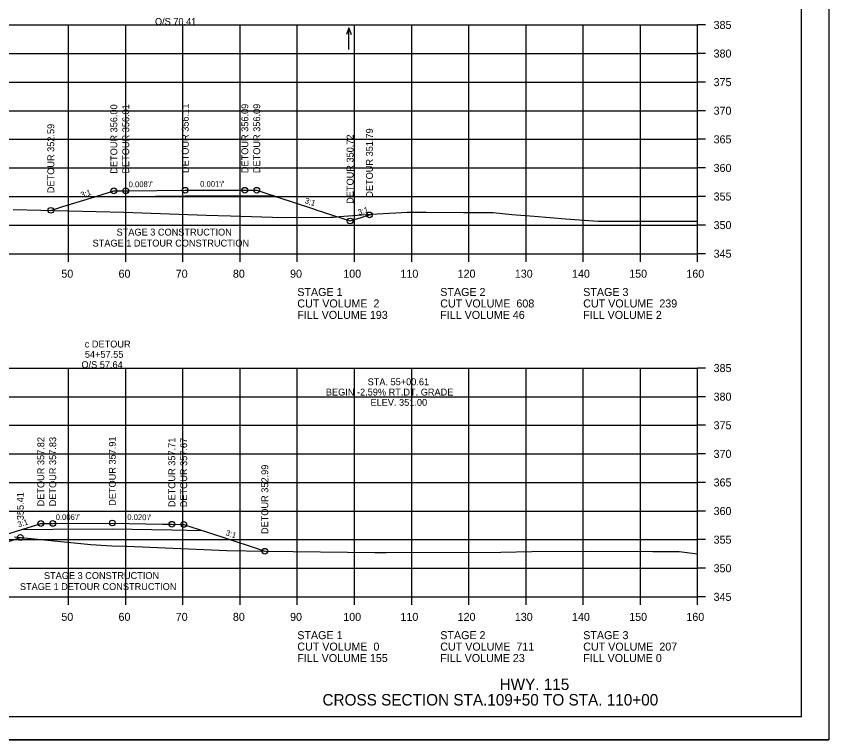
# Model space of a CAD drawing. Extents: x 1630712 to 1632516, y 782146 to 785403.
# Drawn here: x 1632373.8 to 1632515.9, y 783910 to 784036.5 of the extents above; entities that cross this region are included whole.
import ezdxf

# ---------------------------------------------------------------- set-up
doc = ezdxf.new("R2010")
doc.units = 0
for name, color, linetype in [('Notes', 7, 'Continuous'), ('R_Axis', 7, 'Continuous'), ('R_Axis Annot', 7, 'Continuous'), ('R_Border', 7, 'Continuous'), ('R_Detour Subgrade', 7, 'Continuous'), ('R_Detour Surface', 7, 'Continuous'), ('R_Draft', 7, 'Continuous'), ('R_Exist Surface', 7, 'Continuous'), ('R_Fin Surface', 7, 'Continuous'), ('R_Grid', 7, 'Continuous'), ('R_No Plot', 7, 'Continuous'), ('R_Water Annot', 7, 'Continuous'), ('R_Xsect Elev', 7, 'Continuous'), ('R_Xsect Elev Detour', 7, 'Continuous'), ('R_Xsect Slope', 7, 'Continuous')]:
    doc.layers.add(name, color=color, linetype=linetype)

msp = doc.modelspace()

# ---------------------------------------------------------------- linework, layer by layer
at = {"layer": 'R_Axis'}
for p, q in [((1632492.96, 783994.96), (1632492.96, 784034.96)), ((1632494.36, 784034.96), (1632492.96, 784034.96)), ((1632494.36, 784029.96), (1632492.96, 784029.96)), ((1632494.36, 784024.96), (1632492.96, 784024.96)), ((1632494.36, 784019.96), (1632492.96, 784019.96)), ((1632494.36, 784014.96), (1632492.96, 784014.96)), ((1632494.36, 784009.96), (1632492.96, 784009.96)), ((1632494.36, 784004.96), (1632492.96, 784004.96)), ((1632494.36, 783999.96), (1632492.96, 783999.96)), ((1632212.96, 783994.96), (1632492.96, 783994.96)), ((1632382.96, 783993.56), (1632382.96, 783994.96)), ((1632392.96, 783993.56), (1632392.96, 783994.96)), ((1632402.96, 783993.56), (1632402.96, 783994.96)), ((1632412.96, 783993.56), (1632412.96, 783994.96)), ((1632422.96, 783993.56), (1632422.96, 783994.96)), ((1632432.96, 783993.56), (1632432.96, 783994.96)), ((1632442.96, 783993.56), (1632442.96, 783994.96)), ((1632452.96, 783993.56), (1632452.96, 783994.96)), ((1632462.96, 783993.56), (1632462.96, 783994.96)), ((1632472.96, 783993.56), (1632472.96, 783994.96)), ((1632482.96, 783993.56), (1632482.96, 783994.96)), ((1632492.96, 783993.56), (1632492.96, 783994.96)), ((1632494.36, 783994.96), (1632492.96, 783994.96)), ((1632492.96, 783934.96), (1632492.96, 783974.96)), ((1632494.36, 783974.96), (1632492.96, 783974.96)), ((1632494.36, 783969.96), (1632492.96, 783969.96)), ((1632494.36, 783964.96), (1632492.96, 783964.96)), ((1632494.36, 783959.96), (1632492.96, 783959.96)), ((1632494.36, 783954.96), (1632492.96, 783954.96)), ((1632494.36, 783949.96), (1632492.96, 783949.96)), ((1632494.36, 783944.96), (1632492.96, 783944.96)), ((1632494.36, 783939.96), (1632492.96, 783939.96)), ((1632212.96, 783934.96), (1632492.96, 783934.96)), ((1632382.96, 783933.56), (1632382.96, 783934.96)), ((1632392.96, 783933.56), (1632392.96, 783934.96)), ((1632402.96, 783933.56), (1632402.96, 783934.96)), ((1632412.96, 783933.56), (1632412.96, 783934.96)), ((1632422.96, 783933.56), (1632422.96, 783934.96)), ((1632432.96, 783933.56), (1632432.96, 783934.96)), ((1632442.96, 783933.56), (1632442.96, 783934.96)), ((1632452.96, 783933.56), (1632452.96, 783934.96)), ((1632462.96, 783933.56), (1632462.96, 783934.96)), ((1632472.96, 783933.56), (1632472.96, 783934.96)), ((1632482.96, 783933.56), (1632482.96, 783934.96)), ((1632492.96, 783933.56), (1632492.96, 783934.96)), ((1632494.36, 783934.96), (1632492.96, 783934.96))]:
    msp.add_line(p, q, dxfattribs=at)
at = {"layer": 'R_Border'}
for q in [(1632511.14, 784119.42), (1632194.96, 783913.96)]:
    msp.add_line((1632511.14, 783913.96), q, dxfattribs=at)
at = {"layer": 'R_Detour Subgrade'}
for points in [[(1632387.55, 784004.92), (1632392.96, 784004.97), (1632403.37, 784005.06), (1632413.79, 784005.05), (1632418.9, 784005.05)], [(1632374.78, 783946.75), (1632380.19, 783946.79), (1632390.61, 783946.87), (1632401.02, 783946.66), (1632406.3, 783946.57)]]:
    msp.add_lwpolyline(points, dxfattribs=at)
at = {"layer": 'R_Detour Surface'}
for points in [[(1632379.86, 784002.54), (1632381.97, 784003.2), (1632387.55, 784004.92), (1632387.88, 784005.03), (1632390.88, 784005.95), (1632390.9, 784005.95), (1632391.29, 784005.96), (1632392.96, 784005.97), (1632393.49, 784005.97), (1632403.37, 784006.06), (1632403.39, 784006.06), (1632403.58, 784006.06), (1632403.59, 784006.06), (1632413.79, 784006.05), (1632414.84, 784006.05), (1632415.87, 784006.05), (1632417.81, 784005.41), (1632418.9, 784005.05), (1632419.35, 784004.9), (1632419.53, 784004.84), (1632425.78, 784002.79), (1632426.55, 784002.53), (1632427.18, 784002.32), (1632427.37, 784002.26), (1632427.5, 784002.22), (1632432.19, 784000.68), (1632434.13, 784001.29), (1632435.58, 784001.75), (1632436.05, 784001.9)], [(1632370.61, 783945.46), (1632373.86, 783946.47), (1632374.78, 783946.75), (1632377.41, 783947.56), (1632378.11, 783947.78), (1632379.49, 783947.78), (1632380.19, 783947.79), (1632390.6, 783947.87), (1632390.61, 783947.87), (1632399.39, 783947.69), (1632401.02, 783947.66), (1632402.74, 783947.63), (1632403.1, 783947.63), (1632403.83, 783947.39), (1632406.3, 783946.57), (1632406.53, 783946.49), (1632406.92, 783946.36), (1632415.39, 783943.56), (1632417.28, 783942.94)]]:
    msp.add_lwpolyline(points, dxfattribs=at)
at = {"layer": 'R_Exist Surface'}
for points in [[(1632373.29, 784002.71), (1632392.65, 784002.21), (1632407.04, 784001.7), (1632411.25, 784001.61), (1632420.42, 784001.3), (1632428.84, 784001.37), (1632429.31, 784001.35), (1632430.35, 784001.45), (1632435.82, 784001.89), (1632440.17, 784002.11), (1632442.15, 784002.22), (1632443.63, 784002.21), (1632445.47, 784002.2), (1632452.05, 784002.14), (1632457.19, 784002.14), (1632460.47, 784001.84), (1632464.37, 784001.54), (1632469.84, 784001.08), (1632475.6, 784000.67), (1632483.55, 784000.65), (1632486.52, 784000.65), (1632492.96, 784000.64)], [(1632373.51, 783945.47), (1632386.83, 783944.09), (1632390.55, 783943.86), (1632393.13, 783943.81), (1632410.62, 783943.04), (1632417.43, 783942.94), (1632436.49, 783942.71), (1632437.77, 783942.7), (1632438.5, 783942.7), (1632458.54, 783942.8), (1632464, 783942.87), (1632474.44, 783942.94), (1632485.14, 783942.91), (1632489.76, 783942.9), (1632492.96, 783942.5)]]:
    msp.add_lwpolyline(points, dxfattribs=at)
at = {"layer": 'R_Fin Surface'}
msp.add_lwpolyline([(1632244.19, 783961.28), (1632296.96, 783943.68), (1632310.79, 783947.14), (1632314.96, 783948.18), (1632320.96, 783948.42), (1632332.96, 783948.66), (1632344.96, 783948.42), (1632350.96, 783948.18), (1632355.14, 783947.14), (1632368.96, 783943.68), (1632369.23, 783943.6), (1632374.53, 783945.36)], dxfattribs=at)
at = {"layer": 'R_Grid'}
for p, q in [((1632212.96, 784034.96), (1632492.96, 784034.96)), ((1632382.96, 783994.96), (1632382.96, 784034.96)), ((1632392.96, 783994.96), (1632392.96, 784034.96)), ((1632402.96, 783994.96), (1632402.96, 784034.96)), ((1632412.96, 783994.96), (1632412.96, 784034.96)), ((1632422.96, 783994.96), (1632422.96, 784034.96)), ((1632432.96, 783994.96), (1632432.96, 784034.96)), ((1632442.96, 783994.96), (1632442.96, 784034.96)), ((1632452.96, 783994.96), (1632452.96, 784034.96)), ((1632462.96, 783994.96), (1632462.96, 784034.96)), ((1632472.96, 783994.96), (1632472.96, 784034.96)), ((1632482.96, 783994.96), (1632482.96, 784034.96)), ((1632492.96, 783994.96), (1632492.96, 784034.96)), ((1632212.96, 784029.96), (1632492.96, 784029.96)), ((1632212.96, 784024.96), (1632492.96, 784024.96)), ((1632212.96, 784019.96), (1632492.96, 784019.96)), ((1632212.96, 784014.96), (1632492.96, 784014.96)), ((1632212.96, 784009.96), (1632492.96, 784009.96)), ((1632212.96, 784004.96), (1632492.96, 784004.96)), ((1632212.96, 783999.96), (1632492.96, 783999.96)), ((1632212.96, 783994.96), (1632492.96, 783994.96)), ((1632212.96, 783974.96), (1632492.96, 783974.96)), ((1632382.96, 783934.96), (1632382.96, 783974.96)), ((1632392.96, 783934.96), (1632392.96, 783974.96)), ((1632402.96, 783934.96), (1632402.96, 783974.96)), ((1632412.96, 783934.96), (1632412.96, 783974.96)), ((1632422.96, 783934.96), (1632422.96, 783974.96)), ((1632432.96, 783934.96), (1632432.96, 783974.96)), ((1632442.96, 783934.96), (1632442.96, 783974.96)), ((1632452.96, 783934.96), (1632452.96, 783974.96)), ((1632462.96, 783934.96), (1632462.96, 783974.96)), ((1632472.96, 783934.96), (1632472.96, 783974.96)), ((1632482.96, 783934.96), (1632482.96, 783974.96)), ((1632492.96, 783934.96), (1632492.96, 783974.96)), ((1632212.96, 783969.96), (1632492.96, 783969.96)), ((1632212.96, 783964.96), (1632492.96, 783964.96)), ((1632212.96, 783959.96), (1632492.96, 783959.96)), ((1632212.96, 783954.96), (1632492.96, 783954.96)), ((1632212.96, 783949.96), (1632492.96, 783949.96)), ((1632212.96, 783944.96), (1632492.96, 783944.96)), ((1632212.96, 783939.96), (1632492.96, 783939.96)), ((1632212.96, 783934.96), (1632492.96, 783934.96))]:
    msp.add_line(p, q, dxfattribs=at)
at = {"layer": 'R_No Plot'}
msp.add_line((1632182.56, 783909.98), (1632515.9, 783909.98), dxfattribs=at)
msp.add_lwpolyline([(1632182.56, 784123.31), (1632515.9, 784123.31), (1632515.9, 783909.97), (1632182.56, 783909.97)], close=True, dxfattribs=at)
for centre in [(1632390.88, 784005.95), (1632392.96, 784005.97), (1632403.37, 784006.06), (1632413.79, 784006.05), (1632415.87, 784006.05), (1632379.86, 784002.54), (1632432.19, 784000.68), (1632435.58, 784001.75), (1632378.11, 783947.78), (1632380.19, 783947.79), (1632390.61, 783947.87), (1632401.02, 783947.66), (1632403.1, 783947.63), (1632374.53, 783945.36), (1632417.28, 783942.94)]:
    msp.add_circle(centre, 0.5, dxfattribs=at)
at = {"layer": 'R_Water Annot'}
for p, q in [((1632431.98, 784034.43), (1632431.56, 784033.27)), ((1632431.98, 784030.66), (1632431.98, 784034.43)), ((1632431.98, 784034.43), (1632432.4, 784033.27))]:
    msp.add_line(p, q, dxfattribs=at)

# ---------------------------------------------------------------- texts
at = {"layer": 'Notes'}
for s, p in [('O/S 70.41', (1632398.07, 784034.96)), ('STAGE 3 CONSTRUCTION', (1632391.36, 783998.13)), ('STAGE 1 DETOUR CONSTRUCTION', (1632387.16, 783996.21)), ('c DETOUR', (1632385.79, 783978.56)), ('54+57.55', (1632385.81, 783976.76)), ('O/S 57.64', (1632385.21, 783974.96)), ('STA. 55+00.61', (1632435.26, 783971.96)), ('BEGIN -2.59% RT.DT. GRADE', (1632427.96, 783970.16)), ('ELEV. 351.00', (1632435.76, 783968.36)), ('STAGE 3 CONSTRUCTION', (1632378.65, 783938.08)), ('STAGE 1 DETOUR CONSTRUCTION', (1632374.45, 783936.16))]:
    msp.add_text(s, height=1.2, dxfattribs=at).set_placement(p)
at = {"layer": 'R_Axis Annot'}
for s, p in [('385', (1632495.76, 784034.26)), ('380', (1632495.76, 784029.26)), ('375', (1632495.76, 784024.26)), ('370', (1632495.76, 784019.26)), ('365', (1632495.76, 784014.26)), ('360', (1632495.76, 784009.26)), ('355', (1632495.76, 784004.26)), ('350', (1632495.76, 783999.26)), ('345', (1632495.76, 783994.26)), ('50', (1632381.7, 783990.76)), ('60', (1632391.7, 783990.76)), ('70', (1632401.7, 783990.76)), ('80', (1632411.7, 783990.76)), ('90', (1632421.7, 783990.76)), ('100', (1632431, 783990.76)), ('110', (1632441, 783990.76)), ('120', (1632451, 783990.76)), ('130', (1632461, 783990.76)), ('140', (1632471, 783990.76)), ('150', (1632481, 783990.76)), ('160', (1632491, 783990.76)), ('STAGE 1', (1632422.96, 783987.56)), ('STAGE 2', (1632447.96, 783987.56)), ('STAGE 3', (1632472.96, 783987.56)), ('CUT VOLUME  2', (1632422.96, 783985.56)), ('CUT VOLUME  608', (1632447.96, 783985.56)), ('CUT VOLUME  239', (1632472.96, 783985.56)), ('FILL VOLUME 193', (1632422.96, 783983.56)), ('FILL VOLUME 46', (1632447.96, 783983.56)), ('FILL VOLUME 2', (1632472.96, 783983.56)), ('385', (1632495.76, 783974.26)), ('380', (1632495.76, 783969.26)), ('375', (1632495.76, 783964.26)), ('370', (1632495.76, 783959.26)), ('365', (1632495.76, 783954.26)), ('360', (1632495.76, 783949.26)), ('355', (1632495.76, 783944.26)), ('350', (1632495.76, 783939.26)), ('345', (1632495.76, 783934.26)), ('50', (1632381.7, 783930.76)), ('60', (1632391.7, 783930.76)), ('70', (1632401.7, 783930.76)), ('80', (1632411.7, 783930.76)), ('90', (1632421.7, 783930.76)), ('100', (1632431, 783930.76)), ('110', (1632441, 783930.76)), ('120', (1632451, 783930.76)), ('130', (1632461, 783930.76)), ('140', (1632471, 783930.76)), ('150', (1632481, 783930.76)), ('160', (1632491, 783930.76)), ('STAGE 1', (1632422.96, 783927.56)), ('STAGE 2', (1632447.96, 783927.56)), ('STAGE 3', (1632472.96, 783927.56)), ('CUT VOLUME  0', (1632422.96, 783925.56)), ('CUT VOLUME  711', (1632447.96, 783925.56)), ('CUT VOLUME  207', (1632472.96, 783925.56)), ('FILL VOLUME 155', (1632422.96, 783923.56)), ('FILL VOLUME 23', (1632447.96, 783923.56)), ('FILL VOLUME 0', (1632472.96, 783923.56))]:
    msp.add_text(s, height=1.4, dxfattribs=at).set_placement(p)
at = {"layer": 'R_Draft'}
for s, p in [('HWY. 115', (1632458.34, 783918.67)), ('CROSS SECTION STA.109+50 TO STA. 110+00', (1632427.36, 783915.96))]:
    msp.add_text(s, height=2, dxfattribs=at).set_placement(p)
at = {"layer": 'R_Xsect Elev'}
msp.add_text('355.41', height=1.2, rotation=90, dxfattribs=at).set_placement((1632375.13, 783948.36))
at = {"layer": 'R_Xsect Elev Detour'}
for s, p in [('DETOUR 356.00', (1632391.48, 784008.95)), ('DETOUR 356.01', (1632393.56, 784008.97)), ('DETOUR 356.11', (1632403.97, 784009.06)), ('DETOUR 356.09', (1632414.39, 784009.05)), ('DETOUR 356.09', (1632416.47, 784009.05)), ('DETOUR 352.59', (1632380.46, 784005.54)), ('DETOUR 351.79', (1632436.18, 784004.75)), ('DETOUR 350.72', (1632432.79, 784003.68)), ('DETOUR 357.82', (1632378.71, 783950.78)), ('DETOUR 357.83', (1632380.79, 783950.79)), ('DETOUR 357.91', (1632391.21, 783950.87)), ('DETOUR 357.71', (1632401.62, 783950.66)), ('DETOUR 357.67', (1632403.7, 783950.63)), ('DETOUR 352.99', (1632417.88, 783945.94))]:
    msp.add_text(s, height=1.2, rotation=90, dxfattribs=at).set_placement(p)
at = {"layer": 'R_Xsect Slope'}
for s, rotation, p in [("0.008'/'", 0.4951, (1632393.47, 784006.58)), ("0.001'/'", 359.9326, (1632405.97, 784006.66)), ('3:1', 17.2008, (1632385.22, 784004.72)), ('3:1', 341.7856, (1632424.18, 784003.84)), ('3:1', 17.4935, (1632433.73, 784001.69)), ("0.006'/'", 0.4203, (1632380.71, 783948.39)), ("0.020'/'", 358.8916, (1632393.22, 783948.42)), ('3:1', 17.1392, (1632374.21, 783947.1)), ('3:1', 341.7201, (1632410.35, 783945.76))]:
    msp.add_text(s, height=1, rotation=rotation, dxfattribs=at).set_placement(p)

doc.saveas('drawing.dxf')
